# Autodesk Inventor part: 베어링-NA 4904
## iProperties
IsCustomPart: 1
Company: 한국ATC센터
Created: 2009-02
Part Number: 베어링-NA 4904
Material: 강, 연강
Description: 니들 롤러 베어링 - 경계 치수 및 공차
Document SubType Name: Modeling
Standard: KS B 2029
Designer: KYOUNG IL JANG
Standards Organization: KS
Language: ko-KR
Size Designation: NA 4904 - 20 x 37 x 17
Categories: <MemberInstance><Categories><Category DisplayName="샤프트 부품" InternalName="7f7aeb1f-a693-4053-b835-cee3144e0d98" Mnemonic="SHFT"><Category DisplayName="베어링" Inter
Density: 7.86 g/cm^3
Mass: 73.0306 g
Surface Area: 90.2463 cm^2
Volume: 9.29143 cm^3
Vendor: CBT Solutions
Author: KYOUNG IL JANG
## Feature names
1. IDS_ARRAYROLLER[SIMPL:T] [Circular Pattern]
